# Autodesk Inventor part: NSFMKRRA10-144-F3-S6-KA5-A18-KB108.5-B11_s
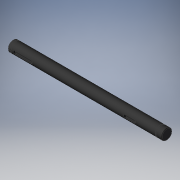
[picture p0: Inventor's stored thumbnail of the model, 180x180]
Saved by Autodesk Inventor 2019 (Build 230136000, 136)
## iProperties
Created: 2022-11
Part Number: NSFMKRRA10-144-F3-S6-KA5-A18-KB108.5-B11_s
Material: Generic
Catalog Web Link: www.cadenas.de
Description: NSFMKRR, SFMKRR, PSFMKRR, SSFMKRR, NSFHKRR, SFHKRR, PSFHKRR, SSFHKRR, NSFGKRR, SFGKRR, PSFGKRR, SSFGKRR, NSFMKRRA, SFMKRRA, PSFMKRRA, SSFMKRRA, NSFHKRRA, SFHKRR
Vendor: MISUMI
Document SubType Name: Modeling
Designer: psAdmin
Manufacturer: MISUMI
Mass: 11.1444 g
Surface Area: 47.8647 cm^2
Volume: 11.1444 cm^3
Density: 1 g/cm^3
Appearance: PSOLRGB-175-175-175
Category: PARTsolutions
Company: MISUMI
Title: NSFMKRRA10-144-F3-S6-KA5-A18-KB108.5-B11
Author: Cadenas PARTsolutions
Comments: Rotary Shafts - Retaining Ring Grooves on Both Ends with Keyway -
PSOL_IDENT_0: {$CADENAS_DATA/23d-libs/misumi/metric/11_rotary_shafts/11_components/psfgkrr/psfgkrr.prj},638 {VTYP=
PSOL_IDENT_1: 3D},{NB=NSFMKRRA10-144-F3-S6-KA5-A18-KB108.5-B11_s},{LINA=NSFMKRRA10-144-F3-S6-KA5-A18-KB108.5-B11},
PSOL_IDENT_2: {NN=NSFMKRR, SFMKRR, PSFMKRR, SSFMKRR, NSFHKRR, SFHKRR, PSFHKRR, SSFHKRR, NSFGKRR, SFGKRR, PSFGKRR,
PSOL_IDENT_3: SSFGKRR, NSFMKRRA, SFMKRRA, PSFMKRRA, SSFMKRRA, NSFHKRRA, SFHKRRA, PSFHKRRA, SSFHKRRA, NSFGKRRA, SFG
PSOL_IDENT_4: KRRA, PSFGKRRA, SSFGKRRA_shaft},{DATE=25.01.2022 23:09:52},{GEOMDATE=05.02.2021 08:15:17},{VERSION=}
PSOL_IDENT_5: ,{LINEID=30},{WBVAR=TS,TYS,MAT,ST,ALT1,L,F,S,NOK,KA,A,KB,B,KC,C,ALT3,FC,GALT3,WFC,J,WALT3,V,ALT4,SFC
PSOL_IDENT_6: ,SG,AG,ALT10,KWC,ALT11,WC,ALT5,UC,ALT7,SC,ALT32,CD},{WBNUMERIC=L,F,S,KA,A,KB,B,KC,C,FC,GALT3,WFC,J,W
PSOL_IDENT_7: ALT3,V,SFC,SG,AG,KWC,WC,UC,SC}  {NB=NSFMKRRA10-144-F3-S6-KA5-A18-KB108.5-B11_s},{LINA=NSFMKRRA10-144
PSOL_IDENT_8: -F3-S6-KA5-A18-KB108.5-B11},{KT=DUMMY},{PN=NSFMKRRA10-144-F3-S6-KA5-A18-KB108.5-B11},{TS=A},{TSALG=''
PSOL_IDENT_9: ,'Standard','A','Retaining Ring'},{TYS=M},{TYSALG= 'M','h9 (Cold-drawn)','H','h7 (Ground)','G','g6 (
PSOL_IDENT_10: Ground)' },{MAT=S45C},{MATALG= 'S45C','S45C Equivalent', 'SUS304','304 Stainless Steel' },{ST=},{STA
PSOL_IDENT_11: LG= '','-','BO','Black Oxide', 'ENP','Electroless Nickel Plating' },{TYPE=NSFMKRR},{D=10},{ALT1=},{L
PSOL_IDENT_12: KCMAX=799.9},{L=144.0},{LALG=[15:800/0.1]},{LMIN=15},{LMAX=800},{F=3.0},{FALG=[3:139/0.1]},{FMIN=3},
PSOL_IDENT_13: {FMAX1=135.8},{FMIN2=6.2},{FMAX2=139},{S=6.0},{SALG=[3:139/0.1]},{SMIN1=3},{SMAX1=134},{SMIN2=6.2},{
PSOL_IDENT_14: SMAX2=139},{DD=9.6},{MM=1.15},{MMALG=1.2},{MMJ=2},{NOK=2},{NOKALG= '1', 'with 1 Key Groove', '2'  , '
PSOL_IDENT_15: with 2 Key Grooves', '3'  , 'with 3 Key Grooves'},{CIFNOK1=0},{CIFNOK2=3},{CIFNOK3=0},{TOL1=0},{TOL2=
PSOL_IDENT_16: 3},{TOL3=0},{BB=3},{TT=1.8},{KA=5.0},{KAALG=[5:128/0.1]},{KAMIN1=0},{KAMIN2=5},{KAMIN3=141.2},{KAMAX
PSOL_IDENT_17: 1=-1000},{KAMAX2=128},{KAMAX3=-1000},{A=18.0},{AALG=[3:100/0.1]},{AMIN=3},{AMAX=100},{AMAX1=-1000},{
PSOL_IDENT_18: AMAX2=100},{AMAX3=-1000},{KAPN=-KA5-A18},{KB=108.5},{KBALG=[25:133/0.1]},{KBMIN1=25},{KBMIN2=25},{KB
PSOL_IDENT_19: MIN3=141.2},{KBMAX1=-1000},{KBMAX2=133},{KBMAX3=-1000},{B=11.0},{BALG=[3:27.5/0.1]},{BMIN=3},{BMAX=2
PSOL_IDENT_20: 7.5},{BMAX1=-1000},{BMAX2=27.5},{BMAX3=-1000},{KBPN=-KB108.5-B11},{KC=0.0},{KCALG=[0]},{KCMIN1=121.5
PSOL_IDENT_21: },{KCMIN2=121.5},{KCMIN3=141.2},{KCMAX1=-1000},{KCMAX2=-1000},{KCMAX3=-1000},{C=0.0},{CALG=0},{CMIN=
PSOL_IDENT_22: 3},{CMAX=-1000},{CMAX1=-1000},{CMAX2=-1000},{CMAX3=-1000},{CIFKA=5},{CIFKB=3},{CIFKC=3},{KCPN=},{ALT
PSOL_IDENT_23: 3=},{ALT3ALG= '', 'w/o Set Screw Flat','FC','with FC (Adds a Set Screw Flat)','WFC','with WFC (Adds
PSOL_IDENT_24: Two Set Screw Flats)','FCWFC','with FC + WFC (Adds Three Set Screw Flats)' },{ALT3PN=},{FC=0},{FCALG=
PSOL_IDENT_25: [0]},{FCMIN=0},{FCMAX=143},{GALT3=0},{GALT3ALG=[0]},{GALT3MIN=1},{GALT3MAX=70},{GALT3MAX2=70},{GALT3
PSOL_IDENT_26: MAX3=70},{WFC=0},{WFCALG=[0]},{WFCMIN=0},{WFCMIN2=2},{WFCMAX=140},{WFCMAX2=-3},{WFCMAX3=-4},{J=0},{J
PSOL_IDENT_27: ALG=[0]},{JMIN=1},{JMAX=70},{JMAX2=-2},{JMAX3=-5},{WALT3=0},{WALT3ALG=[0]},{WALT3MIN=0},{WALT3MIN2=1
PSOL_IDENT_28: 46},{WALT3MAX=141},{WALT3MAX2=141},{V=0},{VALG=[0]},{VMIN=1},{VMAX=70},{VMAX2=70},{CIFFC=0},{ALT4=},
PSOL_IDENT_29: {ALT4ALG= '', 'w/o SFC (2 Set Screw Flats (Angle Specified))', 'SFC'  , 'with SFC (2 Set Screw Flats
PSOL_IDENT_30: (Angle Specified))'},{ALT4PN=},{SFC=0},{SFCALG=[0]},{SFCMIN=0},{SFCMAX=143},{SG=0},{SGALG=[0]},{SGM
PSOL_IDENT_31: IN=1},{SGMAX=70},{AG=0},{AGALG=[0]},{H=0},{CIFSFC=0},{ALT10=},{ALT10ALG= '','Not applicable' },{KWC=
PSOL_IDENT_32: 0},{KWCALG=[0]},{KWCMIN=1},{KWCMAX=0},{WALT10=8},{ALT10PN=},{ALT11=},{ALT11ALG= '','Not applicable'
PSOL_IDENT_33: },{WC=0.0},{WCALG=[0]},{ALT11PN=},{ALT5=},{ALT5ALG= '', 'w/o UC (Slit Cam Groove)', 'UC', 'with UC (
PSOL_IDENT_34: Slit Cam Groove)'},{ALT5PN=},{UC=0},{UCALG=[0]},{UCMIN=1},{UCMAX=138},{DDALT5=0},{LL1=0},{ALT7=},{AL
PSOL_IDENT_35: T7ALG= '', 'w/o SC (Wrench Flats)', 'SC', 'with SC (Wrench Flats)'},{ALT7PN=},{SC=0},{SCALG=[0]},{SC
PSOL_IDENT_36: MIN=0},{SCMAX=136},{LL2=0},{LL2ALG=8},{WALT7=0},{CIFSC=0},{ALT32=},{ALT32ALG= '','w/o CD (Changes Pa
PSOL_IDENT_37: rt D Chamfering)','CD','with CD (Changes Part D Chamfering)' },{CD=},{CDALG= '','N/A' },{CD3D=0.5},{
PSOL_IDENT_38: ALT32PN=},{CIF323R=0},{CIF323L=0},{CIF324R=0},{CIF324L=0},{CIF3210=0},{CIF32F=0},{CIF32S=0},{ERRORPN=
PSOL_IDENT_39: },{ERRORKGALT3=OK},{ERRORKGALT4=OK},{ERRORKGALT5=OK},{ERRORKGALT7=OK},{ERRORKGALT10=OK},{ERRORRALT3=
PSOL_IDENT_40: OK},{ERRORRALT4=NG},{ERRORRALT5=NG},{ERRORRALT7=NG},{ERRORRALT10=OK},{ERRORALT34=OK},{ERRORALT35=OK}
PSOL_IDENT_41: ,{ERRORALT37=OK},{ERRORALT310=OK},{ERRORALT45=OK},{ERRORALT47=OK},{ERRORALT410=OK},{ERRORALT57=OK},{
PSOL_IDENT_42: ERRORALT510=OK},{ERRORALT710=OK},{PCUT3D=0},{QCUT3D=0},{TTALT2=1.8},{BBALT2=3}
NB: NSFMKRRA10-144-F3-S6-KA5-A18-KB108.5-B11_s
NN: NSFMKRR, SFMKRR, PSFMKRR, SSFMKRR, NSFHKRR, SFHKRR, PSFHKRR, SSFHKRR, NSFGKRR, SFGKRR, PSFGKRR, SSFGKRR, NSFMKRRA, SFMKRRA, PSFMKRRA, SSFMKRRA, NSFHKRRA, SFHKRR
NT: Rotary Shafts - Retaining Ring Grooves on Both Ends with Keyway -
NBSYN: $PN._s
LINA: NSFMKRRA10-144-F3-S6-KA5-A18-KB108.5-B11
CATALOG: Misumi
PN: NSFMKRRA10-144-F3-S6-KA5-A18-KB108.5-B11
TS: Retaining Ring
TYS: h9 (Cold-drawn)
MAT: S45C Equivalent
ST: -
D: 10
ALT1: w/o LKC (Changes L Tolerance)
L: 144
F: 3
S: 6
DD: 9.6
MM: 1.15
NOK: with 2 Key Grooves
KA: 5
A: 18
KB: 108.5
B: 11
KC: 0
C: 0
ALT3: w/o Set Screw Flat
FC: 0
GALT3: 0
WFC: 0
J: 0
WALT3: 0
V: 0
ALT4: w/o SFC (2 Set Screw Flats (Angle Specified))
SFC: 0
SG: 0
AG: 0
H: 0
ALT10: Not applicable
KWC: 0
ALT11: Not applicable
WC: 0
ALT5: w/o UC (Slit Cam Groove)
UC: 0
DDALT5: 0
LL1: 0
ALT7: w/o SC (Wrench Flats)
SC: 0
LL2: 0
WALT7: 0
ALT32: w/o CD (Changes Part D Chamfering)
CD: N/A
SUPPLIER: MISUMI
ARTICLENO: NSFMKRRA10-144-F3-S6-KA5-A18-KB108.5-B11_s
BOMINFO: NSFMKRRA10-144-F3-S6-KA5-A18-KB108.5-B11
CREATOR: CADENAS GmbH
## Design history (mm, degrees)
sketch "Sketch_1"
  geometry: L1 (-144, 0)-(0, 0); L2 (0, 0)-(0, -4.5); L3 (0, -4.5)-(-0.5, -5); L4 (-0.5, -5)-(-143.5, -5); L5 (-143.5, -5)-(-144, -4.5); L6 (-144, -4.5)-(-144, 0); L7 (-144, 0)-(0, 0)
  constraints: 14 end point
revolve "Revolution1" sketch "Sketch_1" stored, may be unused: angle "d0" = 360 deg
sketch "Sketch_27"
  geometry: L1 (144, 0)-(-144, 0); L2 (1.85, 9.6)-(1.85, 4.8); L3 (1.85, 4.8)-(3, 4.8); L4 (3, 4.8)-(3, 9.6); L5 (3, 9.6)-(1.85, 9.6)
  constraints: 10 end point
revolve "Revolution2" sketch "Sketch_27" stored, may be unused: angle "d1" = 360 deg
sketch "Sketch_39"
  geometry: L1 (144, 0)-(-144, 0); L2 (138, 9.6)-(138, 4.8); L3 (138, 4.8)-(139.15, 4.8); L4 (139.15, 4.8)-(139.15, 9.6); L5 (139.15, 9.6)-(138, 9.6)
  constraints: 10 end point
revolve "Revolution3" sketch "Sketch_39" stored, may be unused: angle "d2" = 360 deg
sketch "_____7"
  geometry: L1 (6.5, -1.5)-(21.5, -1.5); L2 (21.5, 1.5)-(6.5, 1.5); A1 r 1.5 centre (6.5, 0) between (6.5, 1.5) and (6.5, -1.5); A2 r 1.5 centre (21.5, 0) between (21.5, -1.5) and (21.5, 1.5)
  constraints: 4 end point, 4 point on circle, 2 centre point
extrude "Extrusion1" cut sketch "_____7" distance "d3" = 1.8; taper "d4" = 0 deg
sketch "_____10"
  geometry: L1 (110, -1.5)-(118, -1.5); L2 (118, 1.5)-(110, 1.5); A1 r 1.5 centre (110, 0) between (110, 1.5) and (110, -1.5); A2 r 1.5 centre (118, 0) between (118, -1.5) and (118, 1.5)
  constraints: 4 end point, 4 point on circle, 2 centre point
extrude "Extrusion2" cut sketch "_____10" distance "d5" = 1.8; taper "d6" = 0 deg
node "to_rring_1_XY"
node "to_rring_1_YZ"
node "to_rring_1_ZX"
node "to_rring_1_X"
node "to_rring_1_Y"
node "to_rring_1_Z"
node "to_rring_1_Center"
node "to_rring_2_XY"
node "to_rring_2_YZ"
node "to_rring_2_ZX"
node "to_rring_2_X"
node "to_rring_2_Y"
node "to_rring_2_Z"
node "to_rring_2_Center"
body "Solid1"
